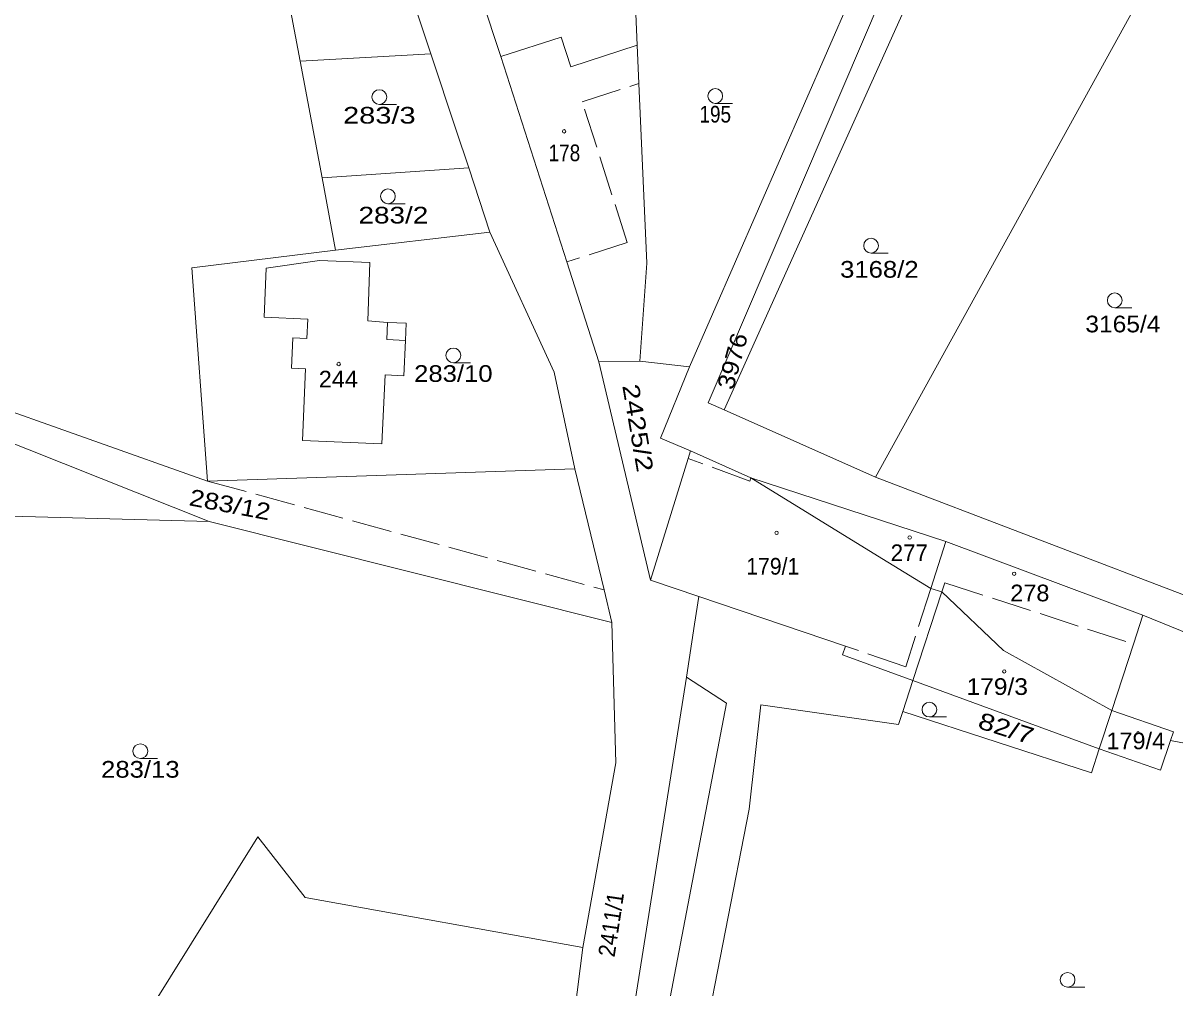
# Model space of a CAD drawing. Extents: x -590528 to -586543, y -1119609 to -1116685.
# Drawn here: x -589035.6 to -588918.3, y -1118317.2 to -1118218.9 of the extents above; entities that cross this region are included whole.
import ezdxf
from ezdxf.enums import TextEntityAlignment as Align

# ---------------------------------------------------------------- set-up
doc = ezdxf.new("R2010")
doc.units = 0
doc.header["$LTSCALE"] = 0.68
doc.linetypes.add('LONG_DASHED', pattern=[7.5, 6, -1.5])
for name, color, linetype, lineweight in [('1', 7, 'Continuous', 13), ('2', 7, 'LONG_DASHED', 13), ('3', 7, 'Continuous', 13), ('6', 7, 'Continuous', 13)]:
    doc.layers.add(name, color=color, linetype=linetype, lineweight=lineweight)

msp = doc.modelspace()

# ---------------------------------------------------------------- linework, layer by layer
at = {"layer": '1'}
for p, q in [((-588964.17, -1118258.31), (-588939.08, -1118202.48)), ((-588992.82, -1118204.5), (-588986.92, -1118222.32)), ((-588919.7, -1118212.47), (-588948.76, -1118265.18)), ((-588973.03, -1118221.16), (-588973.28, -1118215.23)), ((-588967.71, -1118253.93), (-588950.77, -1118215.1)), ((-588947.96, -1118215.85), (-588965.82, -1118257.59)), ((-588973.03, -1118221.16), (-588979.81, -1118223.35)), ((-588972.86, -1118225.05), (-588973.03, -1118221.16)), ((-589007.39, -1118222.8), (-588994.05, -1118222.05)), ((-589005.15, -1118234.69), (-589007.39, -1118222.8)), ((-588986.92, -1118222.32), (-588980.2, -1118243.24)), ((-588972.07, -1118243.38), (-588972.86, -1118225.05)), ((-589018.4, -1118243.85), (-589016.81, -1118265.57)), ((-588976.94, -1118253.44), (-588980.2, -1118243.24)), ((-589008.26, -1118254.08), (-589008.14, -1118250.98)), ((-589008.14, -1118250.98), (-589006.69, -1118251.04)), ((-588976.94, -1118253.44), (-588971.68, -1118275.66)), ((-588972.77, -1118253.36), (-588967.71, -1118253.93)), ((-589006.82, -1118254.14), (-589008.26, -1118254.08)), ((-589006.82, -1118254.14), (-589007.15, -1118261.43)), ((-588967.71, -1118253.93), (-588970.66, -1118261.21)), ((-588999.07, -1118261.78), (-588998.73, -1118254.76)), ((-588998.73, -1118254.76), (-588996.83, -1118254.85)), ((-588999.07, -1118261.78), (-589007.15, -1118261.43)), ((-588970.66, -1118261.21), (-588967.61, -1118262.48)), ((-588967.61, -1118262.48), (-588961.45, -1118265.24)), ((-589016.81, -1118265.57), (-588979.38, -1118264.33)), ((-588905.88, -1118281.56), (-588948.76, -1118265.18)), ((-589016.64, -1118269.69), (-589062.19, -1118268.47)), ((-589016.64, -1118269.69), (-588975.62, -1118280)), ((-588948.55, -1118273.18), (-588943.13, -1118276.52)), ((-588944.95, -1118285.9), (-588942.01, -1118276.88)), ((-588935.73, -1118282.84), (-588942.01, -1118276.88)), ((-588921.53, -1118279.24), (-588892.58, -1118291.03)), ((-588968.01, -1118285.55), (-588967.2, -1118280.15)), ((-588924.7, -1118288.96), (-588922.49, -1118282.18)), ((-588935.73, -1118282.84), (-588924.7, -1118288.96)), ((-588981.91, -1118373.18), (-588968.01, -1118285.55)), ((-588963.96, -1118288.22), (-588968.01, -1118285.55)), ((-588944.95, -1118285.9), (-588945.97, -1118289.05)), ((-588971.3, -1118326.57), (-588963.96, -1118288.22)), ((-588924.7, -1118288.96), (-588918.4, -1118291.14)), ((-588894, -1118296.78), (-588918.7, -1118292.01)), ((-588925.97, -1118292.87), (-588919.74, -1118295.02)), ((-589031.78, -1118334), (-589011.68, -1118301.83)), ((-588982.58, -1118344.54), (-588978.58, -1118313.12))]:
    msp.add_line(p, q, dxfattribs=at)
for points in [[(-589007.39, -1118222.8), (-589010.17, -1118208.04), (-589012.92, -1118193.43)], [(-588991.47, -1118229.81), (-588994.05, -1118222.05), (-588998.82, -1118207.72)], [(-588979.81, -1118223.35), (-588980.78, -1118220.35), (-588986.92, -1118222.32)], [(-588988.04, -1118240.2), (-588990.2, -1118233.66), (-588991.47, -1118229.81)], [(-589003.77, -1118242.05), (-589005.15, -1118234.69), (-588990.2, -1118233.66)], [(-588988.04, -1118240.2), (-589003.77, -1118242.05), (-589018.4, -1118243.85)], [(-588988.04, -1118240.2), (-588981.51, -1118254.49), (-588979.38, -1118264.33), (-588976.42, -1118276.66), (-588975.62, -1118280)], [(-589010.83, -1118243.89), (-589011.05, -1118248.88), (-589006.61, -1118249.09), (-589006.69, -1118251.04)], [(-589010.83, -1118243.89), (-589005.42, -1118243.1), (-589000.29, -1118243.32), (-589000.47, -1118249.26), (-588998.48, -1118249.43), (-588996.58, -1118249.49)], [(-588972.07, -1118243.38), (-588972.77, -1118253.36), (-588976.94, -1118253.44)], [(-589016.64, -1118269.69), (-589064.7, -1118250.56), (-589065.09, -1118248.48), (-589016.81, -1118265.57)], [(-588996.58, -1118249.49), (-588996.66, -1118251.26), (-588996.83, -1118254.85)], [(-588948.76, -1118265.18), (-588964.17, -1118258.31), (-588965.82, -1118257.59)], [(-588967.61, -1118262.48), (-588967.85, -1118263.27), (-588971.68, -1118275.66)], [(-588941.6, -1118271.75), (-588961.45, -1118265.24), (-588948.55, -1118273.18)], [(-588941.6, -1118271.75), (-588943.13, -1118276.52), (-588942.01, -1118276.88)], [(-588922.49, -1118282.18), (-588921.53, -1118279.24), (-588941.6, -1118271.75)], [(-588967.2, -1118280.15), (-588966.77, -1118277.33), (-588971.68, -1118275.66)], [(-588952.12, -1118283.27), (-588951.81, -1118282.41), (-588966.77, -1118277.33)], [(-588975.62, -1118280), (-588975.22, -1118294.29), (-588978.58, -1118313.12)], [(-588925.97, -1118292.87), (-588944.95, -1118285.9), (-588952.12, -1118283.27)], [(-588965.72, -1118328.26), (-588966.44, -1118323.73), (-588961.64, -1118299.01), (-588960.46, -1118288.38), (-588946.41, -1118290.38), (-588945.97, -1118289.05), (-588926.77, -1118295.31)], [(-588926.77, -1118295.31), (-588925.97, -1118292.87), (-588924.7, -1118288.96)], [(-588919.74, -1118295.02), (-588918.7, -1118292.01), (-588918.4, -1118291.14)], [(-588978.58, -1118313.12), (-589006.87, -1118308.02), (-589011.68, -1118301.83)]]:
    msp.add_lwpolyline(points, dxfattribs=at)
at = {"layer": '2'}
for p, q in [((-588978.66, -1118226.92), (-588972.86, -1118225.05)), ((-588974.05, -1118241.27), (-588978.66, -1118226.92)), ((-588974.05, -1118241.27), (-588980.2, -1118243.24)), ((-589016.81, -1118265.57), (-588976.42, -1118276.66)), ((-588941.7, -1118275.93), (-588942.01, -1118276.88)), ((-588941.7, -1118275.93), (-588922.49, -1118282.18))]:
    msp.add_line(p, q, dxfattribs=at)
for points in [[(-588998.48, -1118249.43), (-588998.56, -1118251.16), (-588996.66, -1118251.26)], [(-588961.45, -1118265.24), (-588961.58, -1118265.59), (-588967.85, -1118263.27)], [(-588943.13, -1118276.52), (-588945.68, -1118284.49), (-588951.81, -1118282.41)]]:
    msp.add_lwpolyline(points, dxfattribs=at)
at = {"layer": '6'}
for p, q in [((-588999.31, -1118227.2), (-588997.56, -1118227.2)), ((-588965.09, -1118227.09), (-588963.34, -1118227.09)), ((-588998.44, -1118237.31), (-588996.69, -1118237.31)), ((-588949.21, -1118242.34), (-588947.46, -1118242.34)), ((-588924.39, -1118247.91), (-588922.64, -1118247.91)), ((-588991.77, -1118253.52), (-588990.02, -1118253.52)), ((-588943.27, -1118289.61), (-588941.52, -1118289.61)), ((-589023.66, -1118293.85), (-589021.91, -1118293.85)), ((-588929.19, -1118317.15), (-588927.44, -1118317.15))]:
    msp.add_line(p, q, dxfattribs=at)
for centre, radius in [((-588999.31, -1118226.45), 0.75), ((-588965.09, -1118226.34), 0.75), ((-588980.4902, -1118229.9404), 0.175), ((-588998.44, -1118236.56), 0.75), ((-588949.21, -1118241.59), 0.75), ((-588924.39, -1118247.16), 0.75), ((-588991.77, -1118252.77), 0.75), ((-589003.4502, -1118253.6504), 0.175), ((-588958.8402, -1118270.8504), 0.175), ((-588945.2802, -1118271.3304), 0.175), ((-588934.6402, -1118275.0204), 0.175), ((-588935.6502, -1118284.9704), 0.175), ((-588943.27, -1118288.86), 0.75), ((-588922.0201, -1118291.2102), 0.1172), ((-589023.66, -1118293.1), 0.75), ((-588929.19, -1118316.4), 0.75)]:
    msp.add_circle(centre, radius, dxfattribs=at)

# ---------------------------------------------------------------- texts
at = {"layer": '3'}
for s, width, p in [('283/3', 1.3, (-588999.3105, -1118229.15)), ('195', 0.85, (-588965.0905, -1118229.04)), ('178', 0.85, (-588980.46, -1118232.98)), ('283/2', 1.25, (-588997.88, -1118239.33)), ('3168/2', 1.15, (-588948.3705, -1118244.85)), ('3165/4', 1.1, (-588923.56, -1118250.42)), ('244', 1.05, (-589003.4905, -1118256.04)), ('283/10', 1.15, (-588991.7705, -1118255.47)), ('179/1', 0.95, (-588959.2305, -1118275.11)), ('278', 1.05, (-588933.0405, -1118277.83)), ('179/3', 1.1, (-588936.3605, -1118287.37)), ('179/4', 1.05, (-588922.2495, -1118292.9)), ('283/13', 1.15, (-589023.6605, -1118295.8))]:
    msp.add_text(s, height=1.7, dxfattribs=dict(at, width=width)).set_placement(p, align=Align.CENTER)
for s, rotation, width, p in [('3976', 74.828, 1.15, (-588962.5097, -1118253.5775)), ('2425/2', 279.718, 1.3, (-588973.8054, -1118260.3035)), ('283/12', 349.275, 1.2, (-589014.6822, -1118268.8099)), ('82/7', 342.571, 1.3, (-588935.7051, -1118291.5798)), ('2411/1', 81.475, 0.95, (-588974.8609, -1118310.884))]:
    msp.add_text(s, height=1.7, rotation=rotation, dxfattribs=dict(at, width=width)).set_placement(p, align=Align.CENTER)
msp.add_text('277', height=1.7, dxfattribs=at).set_placement((-588945.32, -1118273.73), align=Align.CENTER)

doc.saveas('drawing.dxf')
